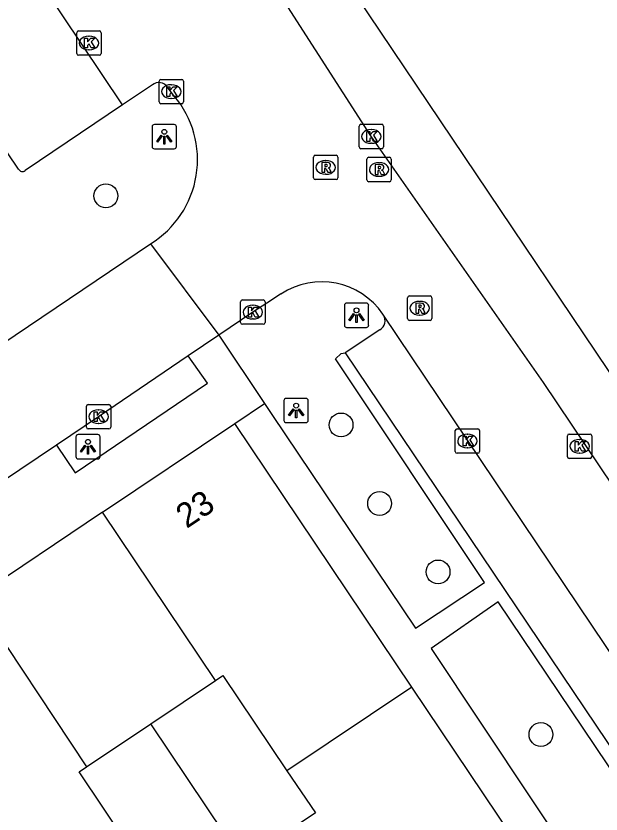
# Model space of a CAD drawing. Extents: x 158797 to 159887, y 384318 to 385255.
# Drawn here: x 159097.22 to 159121.21, y 384860.77 to 384893.48 of the extents above; entities that cross this region are included whole.
import ezdxf

# ---------------------------------------------------------------- set-up
doc = ezdxf.new("R2010")
doc.units = 0
for name, color, linetype in [('IMGEO_Boom', 7, 'Continuous'), ('IMGEO_Kolk', 7, 'Continuous'), ('IMGEO_Lichtpunt', 7, 'Continuous'), ('IMGEO_Pand', 7, 'Continuous'), ('IMGEO_Pand_nummerreeks', 7, 'Continuous'), ('IMGEO_Parkeervlak_open', 7, 'Continuous'), ('IMGEO_Rijbaan_lokaal_open', 7, 'Continuous'), ('IMGEO_Rioolput', 7, 'Continuous'), ('IMGEO_Voetpad_open', 7, 'Continuous')]:
    doc.layers.add(name, color=color, linetype=linetype)

msp = doc.modelspace()

# ---------------------------------------------------------------- linework, layer by layer
at = {"layer": 'IMGEO_Boom'}
for centre in [(159100.907, 384886.106), (159110.551, 384876.715), (159112.132, 384873.497), (159114.529, 384870.689), (159118.749, 384864.027)]:
    msp.add_circle(centre, 0.489, dxfattribs=at)
at = {"layer": 'IMGEO_Kolk'}
for p, q in [((159099.712, 384891.943), (159099.712, 384892.795)), ((159099.787, 384892.869), (159100.639, 384892.869)), ((159100.713, 384892.795), (159100.713, 384891.943)), ((159100.2, 384892.649), (159100.225, 384892.649)), ((159100.223, 384892.089), (159100.198, 384892.089)), ((159100.639, 384891.869), (159099.787, 384891.869)), ((159103.089, 384889.954), (159103.089, 384890.806)), ((159103.164, 384890.88), (159104.016, 384890.88)), ((159104.09, 384890.806), (159104.09, 384889.954)), ((159103.577, 384890.66), (159103.602, 384890.66)), ((159103.6, 384890.1), (159103.575, 384890.1)), ((159104.016, 384889.88), (159103.164, 384889.88)), ((159111.292, 384888.114), (159111.292, 384888.966)), ((159111.367, 384889.04), (159112.219, 384889.04)), ((159111.78, 384888.82), (159111.805, 384888.82)), ((159112.293, 384888.966), (159112.293, 384888.114)), ((159111.803, 384888.26), (159111.778, 384888.26)), ((159112.219, 384888.04), (159111.367, 384888.04)), ((159106.433, 384880.914), (159106.433, 384881.766)), ((159106.508, 384881.84), (159107.36, 384881.84)), ((159106.921, 384881.62), (159106.946, 384881.62)), ((159107.434, 384881.766), (159107.434, 384880.914)), ((159106.944, 384881.06), (159106.919, 384881.06)), ((159107.36, 384880.84), (159106.508, 384880.84)), ((159100.105, 384876.628), (159100.105, 384877.48)), ((159100.18, 384877.554), (159101.032, 384877.554)), ((159100.593, 384877.334), (159100.618, 384877.334)), ((159101.106, 384877.48), (159101.106, 384876.628)), ((159100.616, 384876.774), (159100.591, 384876.774)), ((159101.032, 384876.554), (159100.18, 384876.554)), ((159115.234, 384875.63), (159115.234, 384876.482)), ((159115.309, 384876.556), (159116.161, 384876.556)), ((159115.722, 384876.336), (159115.747, 384876.336)), ((159116.235, 384876.482), (159116.235, 384875.63)), ((159119.91, 384876.341), (159120.762, 384876.341)), ((159119.835, 384875.415), (159119.835, 384876.267)), ((159120.323, 384876.121), (159120.348, 384876.121)), ((159120.836, 384876.267), (159120.836, 384875.415)), ((159115.745, 384875.776), (159115.72, 384875.776)), ((159116.161, 384875.556), (159115.309, 384875.556)), ((159120.762, 384875.341), (159119.91, 384875.341)), ((159120.346, 384875.561), (159120.321, 384875.561))]:
    msp.add_line(p, q, dxfattribs=at)
for points in [[(159099.712, 384891.943), (159099.712, 384892.795)], [(159099.787, 384892.869), (159100.639, 384892.869)], [(159100.713, 384892.795), (159100.713, 384891.943)], [(159100.033, 384892.569), (159100.156, 384892.569), (159100.156, 384892.418), (159100.286, 384892.569), (159100.45, 384892.569), (159100.304, 384892.418), (159100.457, 384892.169), (159100.305, 384892.169), (159100.22, 384892.333), (159100.156, 384892.266), (159100.156, 384892.169), (159100.033, 384892.169), (159100.033, 384892.569)], [(159100.639, 384891.869), (159099.787, 384891.869)], [(159103.089, 384889.954), (159103.089, 384890.806)], [(159103.164, 384890.88), (159104.016, 384890.88)], [(159104.09, 384890.806), (159104.09, 384889.954)], [(159103.41, 384890.58), (159103.533, 384890.58), (159103.533, 384890.429), (159103.663, 384890.58), (159103.827, 384890.58), (159103.681, 384890.429), (159103.834, 384890.18), (159103.682, 384890.18), (159103.597, 384890.344), (159103.533, 384890.277), (159103.533, 384890.18), (159103.41, 384890.18), (159103.41, 384890.58)], [(159104.016, 384889.88), (159103.164, 384889.88)], [(159111.292, 384888.114), (159111.292, 384888.966)], [(159111.367, 384889.04), (159112.219, 384889.04)], [(159112.293, 384888.966), (159112.293, 384888.114)], [(159111.613, 384888.74), (159111.736, 384888.74), (159111.736, 384888.589), (159111.866, 384888.74), (159112.03, 384888.74), (159111.884, 384888.589), (159112.037, 384888.34), (159111.885, 384888.34), (159111.8, 384888.504), (159111.736, 384888.437), (159111.736, 384888.34), (159111.613, 384888.34), (159111.613, 384888.74)], [(159112.219, 384888.04), (159111.367, 384888.04)], [(159106.433, 384880.914), (159106.433, 384881.766)], [(159106.508, 384881.84), (159107.36, 384881.84)], [(159107.434, 384881.766), (159107.434, 384880.914)], [(159106.754, 384881.54), (159106.877, 384881.54), (159106.877, 384881.389), (159107.007, 384881.54), (159107.171, 384881.54), (159107.025, 384881.389), (159107.178, 384881.14), (159107.026, 384881.14), (159106.941, 384881.304), (159106.877, 384881.237), (159106.877, 384881.14), (159106.754, 384881.14), (159106.754, 384881.54)], [(159107.36, 384880.84), (159106.508, 384880.84)], [(159100.105, 384876.628), (159100.105, 384877.48)], [(159100.18, 384877.554), (159101.032, 384877.554)], [(159101.106, 384877.48), (159101.106, 384876.628)], [(159100.426, 384877.254), (159100.549, 384877.254), (159100.549, 384877.103), (159100.679, 384877.254), (159100.843, 384877.254), (159100.697, 384877.103), (159100.85, 384876.854), (159100.698, 384876.854), (159100.613, 384877.018), (159100.549, 384876.951), (159100.549, 384876.854), (159100.426, 384876.854), (159100.426, 384877.254)], [(159101.032, 384876.554), (159100.18, 384876.554)], [(159115.234, 384875.63), (159115.234, 384876.482)], [(159115.309, 384876.556), (159116.161, 384876.556)], [(159116.235, 384876.482), (159116.235, 384875.63)], [(159119.91, 384876.341), (159120.762, 384876.341)], [(159115.555, 384876.256), (159115.678, 384876.256), (159115.678, 384876.105), (159115.808, 384876.256), (159115.972, 384876.256), (159115.826, 384876.105), (159115.979, 384875.856), (159115.827, 384875.856), (159115.742, 384876.02), (159115.678, 384875.953), (159115.678, 384875.856), (159115.555, 384875.856), (159115.555, 384876.256)], [(159119.835, 384875.415), (159119.835, 384876.267)], [(159120.156, 384876.041), (159120.279, 384876.041), (159120.279, 384875.89), (159120.409, 384876.041), (159120.573, 384876.041), (159120.427, 384875.89), (159120.58, 384875.641), (159120.428, 384875.641), (159120.343, 384875.805), (159120.279, 384875.738), (159120.279, 384875.641), (159120.156, 384875.641), (159120.156, 384876.041)], [(159120.836, 384876.267), (159120.836, 384875.415)], [(159116.161, 384875.556), (159115.309, 384875.556)], [(159120.762, 384875.341), (159119.91, 384875.341)]]:
    msp.add_lwpolyline(points, dxfattribs=at)
for centre, start, end in [((159099.789, 384892.793), 91.552, 178.448), ((159099.789, 384892.793), 91.552, 178.448), ((159100.637, 384892.793), 1.552, 88.448), ((159100.637, 384892.793), 1.552, 88.448), ((159099.789, 384891.945), 181.552, 268.448), ((159099.789, 384891.945), 181.552, 268.448), ((159100.637, 384891.945), 271.552, 358.448), ((159100.637, 384891.945), 271.552, 358.448), ((159103.166, 384890.804), 91.552, 178.448), ((159103.166, 384890.804), 91.552, 178.448), ((159104.014, 384890.804), 1.552, 88.448), ((159104.014, 384890.804), 1.552, 88.448), ((159103.166, 384889.956), 181.552, 268.448), ((159103.166, 384889.956), 181.552, 268.448), ((159104.014, 384889.956), 271.552, 358.448), ((159104.014, 384889.956), 271.552, 358.448), ((159111.369, 384888.964), 91.552, 178.448), ((159111.369, 384888.964), 91.552, 178.448), ((159112.217, 384888.964), 1.552, 88.448), ((159112.217, 384888.964), 1.552, 88.448), ((159111.369, 384888.116), 181.552, 268.448), ((159111.369, 384888.116), 181.552, 268.448), ((159112.217, 384888.116), 271.552, 358.448), ((159112.217, 384888.116), 271.552, 358.448), ((159106.51, 384881.764), 91.552, 178.448), ((159106.51, 384881.764), 91.552, 178.448), ((159107.358, 384881.764), 1.552, 88.448), ((159107.358, 384881.764), 1.552, 88.448), ((159106.51, 384880.916), 181.552, 268.448), ((159106.51, 384880.916), 181.552, 268.448), ((159107.358, 384880.916), 271.552, 358.448), ((159107.358, 384880.916), 271.552, 358.448), ((159100.182, 384877.478), 91.552, 178.448), ((159100.182, 384877.478), 91.552, 178.448), ((159101.03, 384877.478), 1.552, 88.448), ((159101.03, 384877.478), 1.552, 88.448), ((159100.182, 384876.63), 181.552, 268.448), ((159100.182, 384876.63), 181.552, 268.448), ((159101.03, 384876.63), 271.552, 358.448), ((159101.03, 384876.63), 271.552, 358.448), ((159115.311, 384876.48), 91.552, 178.448), ((159115.311, 384876.48), 91.552, 178.448), ((159116.159, 384876.48), 1.552, 88.448), ((159116.159, 384876.48), 1.552, 88.448), ((159119.912, 384876.265), 91.552, 178.448), ((159119.912, 384876.265), 91.552, 178.448), ((159120.76, 384876.265), 1.552, 88.448), ((159120.76, 384876.265), 1.552, 88.448), ((159115.311, 384875.632), 181.552, 268.448), ((159115.311, 384875.632), 181.552, 268.448), ((159116.159, 384875.632), 271.552, 358.448), ((159116.159, 384875.632), 271.552, 358.448), ((159119.912, 384875.417), 181.552, 268.448), ((159119.912, 384875.417), 181.552, 268.448), ((159120.76, 384875.417), 271.552, 358.448), ((159120.76, 384875.417), 271.552, 358.448)]:
    msp.add_arc(centre, 0.0765, start, end, dxfattribs=at)
for centre, major_axis, ratio, start_param, end_param in [((159100.199, 384892.369), (-0.387, 0.002), 0.722429, 4.712389, 7.853982), ((159100.224, 384892.369), (-0.39, 0.002), 0.717154, 1.570796, 4.712389), ((159103.576, 384890.38), (-0.387, 0.002), 0.722429, 4.712389, 7.853982), ((159103.601, 384890.38), (-0.39, 0.002), 0.717154, 1.570796, 4.712389), ((159111.779, 384888.54), (-0.387, 0.002), 0.722429, 4.712389, 7.853982), ((159111.804, 384888.54), (-0.39, 0.002), 0.717154, 1.570796, 4.712389), ((159106.92, 384881.34), (-0.387, 0.002), 0.722429, 4.712389, 7.853982), ((159106.945, 384881.34), (-0.39, 0.002), 0.717154, 1.570796, 4.712389), ((159100.592, 384877.054), (-0.387, 0.002), 0.722429, 4.712389, 7.853982), ((159100.617, 384877.054), (-0.39, 0.002), 0.717154, 1.570796, 4.712389), ((159115.721, 384876.056), (-0.387, 0.002), 0.722429, 4.712389, 7.853982), ((159115.746, 384876.056), (-0.39, 0.002), 0.717154, 1.570796, 4.712389), ((159120.322, 384875.841), (-0.387, 0.002), 0.722429, 4.712389, 7.853982), ((159120.347, 384875.841), (-0.39, 0.002), 0.717154, 1.570796, 4.712389)]:
    msp.add_ellipse(centre, major_axis=major_axis, ratio=ratio, start_param=start_param, end_param=end_param, dxfattribs=at)
at = {"layer": 'IMGEO_Lichtpunt'}
for p, q in [((159102.802, 384888.935), (159102.802, 384888.128)), ((159102.802, 384888.935), (159102.802, 384888.128)), ((159103.704, 384889.03), (159102.896, 384889.03)), ((159103.704, 384889.03), (159102.896, 384889.03)), ((159103.798, 384888.128), (159103.798, 384888.935)), ((159103.798, 384888.128), (159103.798, 384888.935)), ((159102.896, 384888.034), (159103.704, 384888.034)), ((159102.896, 384888.034), (159103.704, 384888.034)), ((159110.687, 384881.614), (159110.687, 384880.807)), ((159110.687, 384881.614), (159110.687, 384880.807)), ((159111.589, 384881.709), (159110.781, 384881.709)), ((159111.589, 384881.709), (159110.781, 384881.709)), ((159111.683, 384880.807), (159111.683, 384881.614)), ((159111.683, 384880.807), (159111.683, 384881.614)), ((159110.781, 384880.713), (159111.589, 384880.713)), ((159110.781, 384880.713), (159111.589, 384880.713)), ((159108.209, 384877.711), (159108.209, 384876.904)), ((159108.209, 384877.711), (159108.209, 384876.904)), ((159109.111, 384877.806), (159108.303, 384877.806)), ((159109.111, 384877.806), (159108.303, 384877.806)), ((159109.205, 384876.904), (159109.205, 384877.711)), ((159109.205, 384876.904), (159109.205, 384877.711)), ((159108.303, 384876.81), (159109.111, 384876.81)), ((159108.303, 384876.81), (159109.111, 384876.81)), ((159100.576, 384876.32), (159099.768, 384876.32)), ((159100.576, 384876.32), (159099.768, 384876.32)), ((159099.674, 384876.225), (159099.674, 384875.418)), ((159099.674, 384876.225), (159099.674, 384875.418)), ((159100.67, 384875.418), (159100.67, 384876.225)), ((159100.67, 384875.418), (159100.67, 384876.225)), ((159099.768, 384875.324), (159100.576, 384875.324)), ((159099.768, 384875.324), (159100.576, 384875.324))]:
    msp.add_line(p, q, dxfattribs=at)
for points in [[(159103.176, 384888.599), (159103.215, 384888.571), (159103.027, 384888.309), (159102.989, 384888.336), (159103.176, 384888.599)], [(159103.278, 384888.551), (159103.325, 384888.551), (159103.325, 384888.229), (159103.278, 384888.229), (159103.278, 384888.551)], [(159103.388, 384888.571), (159103.426, 384888.598), (159103.613, 384888.336), (159103.574, 384888.308), (159103.388, 384888.571)], [(159111.061, 384881.278), (159111.1, 384881.25), (159110.912, 384880.988), (159110.874, 384881.015), (159111.061, 384881.278)], [(159111.163, 384881.23), (159111.21, 384881.23), (159111.21, 384880.908), (159111.163, 384880.908), (159111.163, 384881.23)], [(159111.273, 384881.25), (159111.311, 384881.277), (159111.498, 384881.015), (159111.459, 384880.987), (159111.273, 384881.25)], [(159108.583, 384877.375), (159108.622, 384877.347), (159108.434, 384877.085), (159108.396, 384877.112), (159108.583, 384877.375)], [(159108.685, 384877.327), (159108.732, 384877.327), (159108.732, 384877.005), (159108.685, 384877.005), (159108.685, 384877.327)], [(159108.795, 384877.347), (159108.833, 384877.374), (159109.02, 384877.112), (159108.981, 384877.084), (159108.795, 384877.347)], [(159100.048, 384875.889), (159100.087, 384875.861), (159099.899, 384875.599), (159099.861, 384875.626), (159100.048, 384875.889)], [(159100.15, 384875.841), (159100.197, 384875.841), (159100.197, 384875.519), (159100.15, 384875.519), (159100.15, 384875.841)], [(159100.26, 384875.861), (159100.298, 384875.888), (159100.485, 384875.626), (159100.446, 384875.598), (159100.26, 384875.861)]]:
    msp.add_lwpolyline(points, dxfattribs=at)
for centre in [(159103.301, 384888.733), (159111.186, 384881.412), (159108.708, 384877.509), (159100.173, 384876.023)]:
    msp.add_circle(centre, 0.0994, dxfattribs=at)
for centre, start, end in [((159102.896, 384888.935), 90, 180), ((159102.896, 384888.935), 90, 180), ((159103.704, 384888.935), 0, 90), ((159103.704, 384888.935), 0, 90), ((159102.896, 384888.128), 180, 270), ((159102.896, 384888.128), 180, 270), ((159103.704, 384888.128), 270, 0), ((159103.704, 384888.128), 270, 360), ((159110.781, 384881.614), 90, 180), ((159110.781, 384881.614), 90, 180), ((159111.589, 384881.614), 0, 90), ((159111.589, 384881.614), 0, 90), ((159110.781, 384880.807), 180, 270), ((159110.781, 384880.807), 180, 270), ((159111.589, 384880.807), 270, 0), ((159111.589, 384880.807), 270, 360), ((159108.303, 384877.711), 90, 180), ((159108.303, 384877.711), 90, 180), ((159109.111, 384877.711), 0, 90), ((159109.111, 384877.711), 0, 90), ((159108.303, 384876.904), 180, 270), ((159108.303, 384876.904), 180, 270), ((159109.111, 384876.904), 270, 0), ((159109.111, 384876.904), 270, 360), ((159099.768, 384876.225), 90, 180), ((159099.768, 384876.225), 90, 180), ((159100.576, 384876.225), 0, 90), ((159100.576, 384876.225), 0, 90), ((159099.768, 384875.418), 180, 270), ((159099.768, 384875.418), 180, 270), ((159100.576, 384875.418), 270, 0), ((159100.576, 384875.418), 270, 360)]:
    msp.add_arc(centre, 0.0946, start, end, dxfattribs=at)
at = {"layer": 'IMGEO_Pand'}
for points in [[(159100.767, 384873.143), (159106.192, 384876.779)], [(159113.453, 384865.967), (159106.192, 384876.779)], [(159105.395, 384866.238), (159100.767, 384873.143)], [(159095.523, 384869.608), (159100.112, 384862.697)], [(159102.745, 384864.462), (159105.395, 384866.238)], [(159105.395, 384866.238), (159105.703, 384866.444), (159108.332, 384862.541)], [(159113.453, 384865.967), (159108.332, 384862.541)], [(159100.112, 384862.697), (159102.745, 384864.462)], [(159106.543, 384858.824), (159102.745, 384864.462)], [(159101.773, 384859.563), (159099.817, 384862.499), (159100.112, 384862.697)], [(159108.332, 384862.541), (159109.496, 384860.813), (159106.543, 384858.824)]]:
    msp.add_lwpolyline(points, dxfattribs=at)
at = {"layer": 'IMGEO_Parkeervlak_open'}
for points in [[(159097.325, 384887.202), (159090.434, 384897.42), (159086.146, 384903.814)], [(159101.592, 384889.833), (159097.592, 384887.145)], [(159112.146, 384880.619), (159110.716, 384879.672)]]:
    msp.add_lwpolyline(points, dxfattribs=at)
for centre, radius, start, end in [((159097.482, 384887.282), 0.176, 207.1458, 308.7526), ((159111.922, 384880.991), 0.434, 301.0539, 30.2813)]:
    msp.add_arc(centre, radius, start, end, dxfattribs=at)
at = {"layer": 'IMGEO_Rijbaan_lokaal_open'}
for points in [[(159148.203, 384834.797), (159118.86, 384878.459), (159111.767, 384888.566), (159104.966, 384899.16), (159103.806, 384898.409), (159096.869, 384908.495), (159087.727, 384922.129), (159083.943, 384919.604), (159075.859, 384931.636), (159073.188, 384929.845), (159064.372, 384942.983)], [(159101.592, 384889.833), (159089.977, 384907.132)], [(159102.817, 384890.656), (159101.592, 384889.833)], [(159103.711, 384890.196), (159103.435, 384890.565)], [(159024.825, 384831.804), (159044.696, 384845.173), (159051.975, 384850.093), (159072.358, 384863.736), (159083.984, 384871.536), (159097.187, 384880.393), (159102.738, 384884.143)], [(159102.738, 384884.143), (159105.533, 384880.391)], [(159108.084, 384882.083), (159107.695, 384881.824), (159106.934, 384881.34), (159105.533, 384880.391)], [(159112.297, 384881.21), (159112.267, 384881.254)], [(159125.401, 384861.714), (159112.297, 384881.21)], [(159105.533, 384880.391), (159104.286, 384879.547)], [(159104.286, 384879.547), (159100.606, 384877.054), (159098.88, 384875.893)], [(159098.88, 384875.893), (159095.066, 384873.328), (159093.66, 384872.389)]]:
    msp.add_lwpolyline(points, dxfattribs=at)
for centre, radius, start, end in [((159103.083, 384890.317), 0.431, 35.1627, 128.0841), ((159100.622, 384887.588), 4.043, 301.5637, 40.1723), ((159109.753, 384879.538), 3.043, 34.3161, 123.2643)]:
    msp.add_arc(centre, radius, start, end, dxfattribs=at)
at = {"layer": 'IMGEO_Rioolput'}
for p, q in [((159109.495, 384887.772), (159110.347, 384887.772)), ((159109.42, 384886.846), (159109.42, 384887.698)), ((159109.908, 384887.552), (159109.933, 384887.552)), ((159110.421, 384887.698), (159110.421, 384886.846)), ((159111.611, 384886.76), (159111.611, 384887.612)), ((159111.686, 384887.686), (159112.538, 384887.686)), ((159112.099, 384887.466), (159112.124, 384887.466)), ((159112.612, 384887.612), (159112.612, 384886.76)), ((159109.931, 384886.992), (159109.906, 384886.992)), ((159112.122, 384886.906), (159112.097, 384886.906)), ((159110.347, 384886.772), (159109.495, 384886.772)), ((159112.538, 384886.686), (159111.686, 384886.686)), ((159113.277, 384881.075), (159113.277, 384881.927)), ((159113.352, 384882.001), (159114.204, 384882.001)), ((159114.278, 384881.927), (159114.278, 384881.075)), ((159113.765, 384881.781), (159113.79, 384881.781)), ((159113.788, 384881.221), (159113.763, 384881.221)), ((159114.204, 384881.001), (159113.352, 384881.001))]:
    msp.add_line(p, q, dxfattribs=at)
for points in [[(159109.495, 384887.772), (159110.347, 384887.772)], [(159109.42, 384886.846), (159109.42, 384887.698)], [(159110.009, 384887.47), (159109.757, 384887.472), (159109.757, 384887.072)], [(159110.421, 384887.698), (159110.421, 384886.846)], [(159111.611, 384886.76), (159111.611, 384887.612)], [(159111.686, 384887.686), (159112.538, 384887.686)], [(159112.612, 384887.612), (159112.612, 384886.76)], [(159109.757, 384887.072), (159109.881, 384887.072), (159109.881, 384887.234), (159109.892, 384887.234)], [(159109.935, 384887.391), (159109.881, 384887.391), (159109.881, 384887.31)], [(159109.881, 384887.31), (159109.933, 384887.31)], [(159109.939, 384887.205), (159110.01, 384887.072), (159110.15, 384887.072), (159110.085, 384887.198)], [(159112.2, 384887.384), (159111.948, 384887.386), (159111.948, 384886.986)], [(159111.948, 384886.986), (159112.072, 384886.986), (159112.072, 384887.148), (159112.083, 384887.148)], [(159112.126, 384887.305), (159112.072, 384887.305), (159112.072, 384887.224)], [(159112.072, 384887.224), (159112.124, 384887.224)], [(159112.13, 384887.119), (159112.201, 384886.986), (159112.341, 384886.986), (159112.276, 384887.112)], [(159110.347, 384886.772), (159109.495, 384886.772)], [(159112.538, 384886.686), (159111.686, 384886.686)], [(159113.277, 384881.075), (159113.277, 384881.927)], [(159113.352, 384882.001), (159114.204, 384882.001)], [(159114.278, 384881.927), (159114.278, 384881.075)], [(159113.866, 384881.699), (159113.614, 384881.701), (159113.614, 384881.301)], [(159113.792, 384881.62), (159113.738, 384881.62), (159113.738, 384881.539)], [(159113.614, 384881.301), (159113.738, 384881.301), (159113.738, 384881.463), (159113.749, 384881.463)], [(159113.738, 384881.539), (159113.79, 384881.539)], [(159113.796, 384881.434), (159113.867, 384881.301), (159114.007, 384881.301), (159113.942, 384881.427)], [(159114.204, 384881.001), (159113.352, 384881.001)]]:
    msp.add_lwpolyline(points, dxfattribs=at)
for centre, radius, start, end in [((159109.497, 384887.696), 0.0765, 91.552, 178.448), ((159109.497, 384887.696), 0.0765, 91.552, 178.448), ((159110.345, 384887.696), 0.0765, 1.552, 88.448), ((159110.345, 384887.696), 0.0765, 1.552, 88.448), ((159110.008, 384887.36), 0.109, 350.3612, 89.416), ((159111.688, 384887.61), 0.0765, 91.552, 178.448), ((159111.688, 384887.61), 0.0765, 91.552, 178.448), ((159112.536, 384887.61), 0.0765, 1.552, 88.448), ((159112.536, 384887.61), 0.0765, 1.552, 88.448), ((159109.891, 384887.181), 0.0533, 26.0293, 88.6989), ((159109.917, 384887.499), 0.19, 274.7715, 282.9687), ((159109.941, 384887.295), 0.0964, 77.0061, 93.1865), ((159109.955, 384887.352), 0.0378, 276.6634, 79.6772), ((159110.006, 384887.36), 0.112, 277.5842, 350.9817), ((159109.99, 384887.145), 0.108, 29.5134, 73.7905), ((159112.082, 384887.095), 0.0533, 26.0293, 88.6989), ((159112.108, 384887.413), 0.19, 274.7715, 282.9687), ((159112.132, 384887.209), 0.0964, 77.0061, 93.1865), ((159112.146, 384887.266), 0.0378, 276.6634, 79.6772), ((159112.199, 384887.274), 0.109, 350.3612, 89.416), ((159112.197, 384887.274), 0.112, 277.5842, 350.9817), ((159112.181, 384887.059), 0.108, 29.5134, 73.7905), ((159109.497, 384886.848), 0.0765, 181.552, 268.448), ((159109.497, 384886.848), 0.0765, 181.552, 268.448), ((159110.345, 384886.848), 0.0765, 271.552, 358.448), ((159110.345, 384886.848), 0.0765, 271.552, 358.448), ((159111.688, 384886.762), 0.0765, 181.552, 268.448), ((159111.688, 384886.762), 0.0765, 181.552, 268.448), ((159112.536, 384886.762), 0.0765, 271.552, 358.448), ((159112.536, 384886.762), 0.0765, 271.552, 358.448), ((159113.354, 384881.925), 0.0765, 91.552, 178.448), ((159113.354, 384881.925), 0.0765, 91.552, 178.448), ((159114.202, 384881.925), 0.0765, 1.552, 88.448), ((159114.202, 384881.925), 0.0765, 1.552, 88.448), ((159113.798, 384881.524), 0.0964, 77.0061, 93.1865), ((159113.812, 384881.581), 0.0378, 276.6634, 79.6772), ((159113.865, 384881.589), 0.109, 350.3612, 89.416), ((159113.863, 384881.589), 0.112, 277.5842, 350.9817), ((159113.748, 384881.41), 0.0533, 26.0293, 88.6989), ((159113.774, 384881.728), 0.19, 274.7715, 282.9687), ((159113.847, 384881.374), 0.108, 29.5134, 73.7905), ((159113.354, 384881.077), 0.0765, 181.552, 268.448), ((159113.354, 384881.077), 0.0765, 181.552, 268.448), ((159114.202, 384881.077), 0.0765, 271.552, 358.448), ((159114.202, 384881.077), 0.0765, 271.552, 358.448)]:
    msp.add_arc(centre, radius, start, end, dxfattribs=at)
for centre, major_axis, ratio, start_param, end_param in [((159109.907, 384887.272), (-0.387, 0.002), 0.722429, 4.712389, 7.853982), ((159109.932, 384887.272), (-0.39, 0.002), 0.717154, 1.570796, 4.712389), ((159112.098, 384887.186), (-0.387, 0.002), 0.722429, 4.712389, 7.853982), ((159112.123, 384887.186), (-0.39, 0.002), 0.717154, 1.570796, 4.712389), ((159113.764, 384881.501), (-0.387, 0.002), 0.722429, 4.712389, 7.853982), ((159113.789, 384881.501), (-0.39, 0.002), 0.717154, 1.570796, 4.712389)]:
    msp.add_ellipse(centre, major_axis=major_axis, ratio=ratio, start_param=start_param, end_param=end_param, dxfattribs=at)
at = {"layer": 'IMGEO_Voetpad_open'}
for points in [[(159065.557, 384943.772), (159065.871, 384943.305), (159073.613, 384931.81), (159076.292, 384933.589), (159084.288, 384921.691), (159088.084, 384924.2), (159104.197, 384900.201), (159106.267, 384901.604), (159122.968, 384876.772), (159122.184, 384876.186), (159129.189, 384865.748), (159145.236, 384841.838), (159145.281, 384841.77), (159147.886, 384837.889), (159147.91, 384837.853)], [(159105.533, 384880.391), (159107.411, 384877.597)], [(159107.411, 384877.597), (159107.718, 384877.141), (159113.598, 384868.379), (159116.433, 384870.256), (159110.319, 384879.432), (159110.551, 384879.645), (159110.716, 384879.672)], [(159110.716, 384879.672), (159123.335, 384860.933)], [(159098.88, 384875.893), (159099.645, 384874.756), (159105.072, 384878.424), (159104.286, 384879.547)], [(159106.192, 384876.779), (159107.411, 384877.597)], [(159100.767, 384873.143), (159095.523, 384869.608)], [(159123.335, 384860.933), (159123.254, 384860.781), (159122.978, 384860.571), (159116.99, 384869.465), (159114.242, 384867.546), (159122.5, 384855.14)], [(159117.591, 384859.806), (159113.453, 384865.967)]]:
    msp.add_lwpolyline(points, dxfattribs=at)

# ---------------------------------------------------------------- texts
at = {"layer": 'IMGEO_Pand_nummerreeks'}
msp.add_text('23', height=1, rotation=33.8332, dxfattribs=at).set_placement((159104.217, 384872.446))

doc.saveas('drawing.dxf')
